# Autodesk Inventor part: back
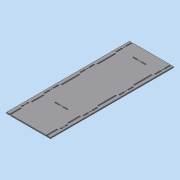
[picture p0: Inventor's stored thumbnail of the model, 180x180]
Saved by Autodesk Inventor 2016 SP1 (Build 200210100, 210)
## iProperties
Created: 2016-06
Part Number: back
Material: Generic
Document SubType Name: Modeling
Designer: Mohamed A.
Density: 1 g/cm^3
Appearance: Default
Author: Mohamed A.
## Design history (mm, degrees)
sketch "Sketch1"
  geometry: L1 (-57, 160)-(57, 160); L2 (57, 160)-(57, -160); L3 (57, -160)-(-57, -160); L4 (-57, -160)-(-57, 160); L5 (-57, 160)-(57, -160); L6 (57, 160)-(-57, -160); 1 further point
  constraints: 12 end point, 2 midpoint, 2 parallel, 1 horizontal, 1 perpendicular
  dimensions: "d0" = 114 distance of L2.end L3.end; "d1" = 320 distance of L1.end L2.end
extrude "Extrusion1" new body sketch "Sketch1" distance "d2" = 3; taper "d3" = 0 deg
sketch "Sketch2"
  geometry: L1 (52, 140.75)-(52, 137.65) reference; L2 (52, 140.75)-(49, 140.75) reference; L3 (49, 137.65)-(49, 140.75) reference; L4 (52, 137.65)-(49, 137.65) reference; L5 (52, 45.05)-(52, 41.95) reference; L6 (52, 45.05)-(49, 45.05) reference; L7 (49, 41.95)-(49, 45.05) reference; L8 (52, 41.95)-(49, 41.95) reference; L9 (-49, 45.05)-(-49, 41.95) reference; L10 (-49, 45.05)-(-52, 45.05) reference; L11 (-52, 41.95)-(-52, 45.05) reference; L12 (-49, 41.95)-(-52, 41.95) reference; L13 (-49, 140.75)-(-49, 137.65) reference; L14 (-49, 140.75)-(-52, 140.75) reference; L15 (-52, 137.65)-(-52, 140.75) reference; L16 (-49, 137.65)-(-52, 137.65) reference; L17 (52, -48.15)-(52, -51.25) reference; L18 (52, -48.15)-(49, -48.15) reference; L19 (49, -51.25)-(49, -48.15) reference; L20 (52, -51.25)-(49, -51.25) reference; L21 (-49, -48.15)-(-49, -51.25) reference; L22 (-49, -48.15)-(-52, -48.15) reference; L23 (-52, -51.25)-(-52, -48.15) reference; L24 (-49, -51.25)-(-52, -51.25) reference; L25 (52, -116.45)-(52, -119.55) reference; L26 (52, -116.45)-(49, -116.45) reference; L27 (49, -119.55)-(49, -116.45) reference; L28 (52, -119.55)-(49, -119.55) reference; L29 (-49, -116.45)-(-49, -119.55) reference; L30 (-49, -116.45)-(-52, -116.45) reference; L31 (-52, -119.55)-(-52, -116.45) reference; L32 (-49, -119.55)-(-52, -119.55) reference; L33 (-49, -114.25)-(-52, -114.25) reference; L34 (-52, -114.25)-(-52, -109) reference; L35 (-52, -109)-(-49, -109) reference; L36 (-49, -109)-(-49, -114.25) reference; L37 (-52, -121.75)-(-49, -121.75) reference; L38 (-49, -121.75)-(-49, -127) reference; L39 (-49, -127)-(-52, -127) reference; L40 (-52, -127)-(-52, -121.75) reference; L41 (-52, 39)-(-49, 39) reference; L42 (-49, 39)-(-49, 25.2) reference; L43 (-49, 25.2)-(-52, 25.2) reference; L44 (-52, 25.2)-(-52, 39) reference; L45 (-49, 48)-(-52, 48) reference; L46 (-52, 48)-(-52, 61.8) reference; L47 (-52, 61.8)-(-49, 61.8) reference; L48 (-49, 61.8)-(-49, 48) reference; L49 (-52, 134.7)-(-49, 134.7) reference; L50 (-49, 134.7)-(-49, 118.4) reference; L51 (-49, 118.4)-(-52, 118.4) reference; L52 (-52, 118.4)-(-52, 134.7) reference; L53 (-49, 143.7)-(-52, 143.7) reference; L54 (-52, 143.7)-(-52, 160) reference; L55 (-52, 160)-(-49, 160) reference; L56 (-49, 160)-(-49, 143.7) reference; L57 (-52, -54.2)-(-49, -54.2) reference; L58 (-49, -54.2)-(-49, -68) reference; L59 (-49, -68)-(-52, -68) reference; L60 (-52, -68)-(-52, -54.2) reference; L61 (-49, -45.2)-(-52, -45.2) reference; L62 (-52, -45.2)-(-52, -31.4) reference; L63 (-52, -31.4)-(-49, -31.4) reference; L64 (-49, -31.4)-(-49, -45.2) reference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; C1 r 1.4 at (50.5, 139.2); C2 r 1.4 at (-50.5, 139.2); C3 r 1.4 at (-50.5, 43.5); C4 r 1.4 at (50.5, 43.5); C5 r 1.4 at (50.5, -49.7); C6 r 1.4 at (-50.5, -49.7); C7 r 1.4 at (50.5, -118); C8 r 1.4 at (-50.5, -118); C9 r 1.4 at (0, 128.5); C10 r 1.4 at (0, -74.5)
  constraints: 224 end point, 56 horizontal, 56 vertical, 10 centre point, 112 other
  dimensions: "d10" = 2.8 diameter of C1; "d11" = 2.8 diameter of C2; "d12" = 2.8 diameter of C3; "d13" = 2.8 diameter of C4; "d14" = 2.8 diameter of C5; "d15" = 2.8 diameter of C6; "d16" = 2.8 diameter of C7; "d17" = 2.8 diameter of C8; "d18" = 2.8 diameter of C9; "d19" = 2.8 diameter of C10
extrude "Extrusion2" cut sketch "Sketch2" distance "d8" = 10; taper "d9" = 0 deg
body "Solid1"
node "Reference6"
node "Reference7"
node "Reference8"
node "Reference9"
node "Reference10"
node "Reference11"
node "Reference12"
node "Reference13"
node "Reference14"
node "Reference15"
